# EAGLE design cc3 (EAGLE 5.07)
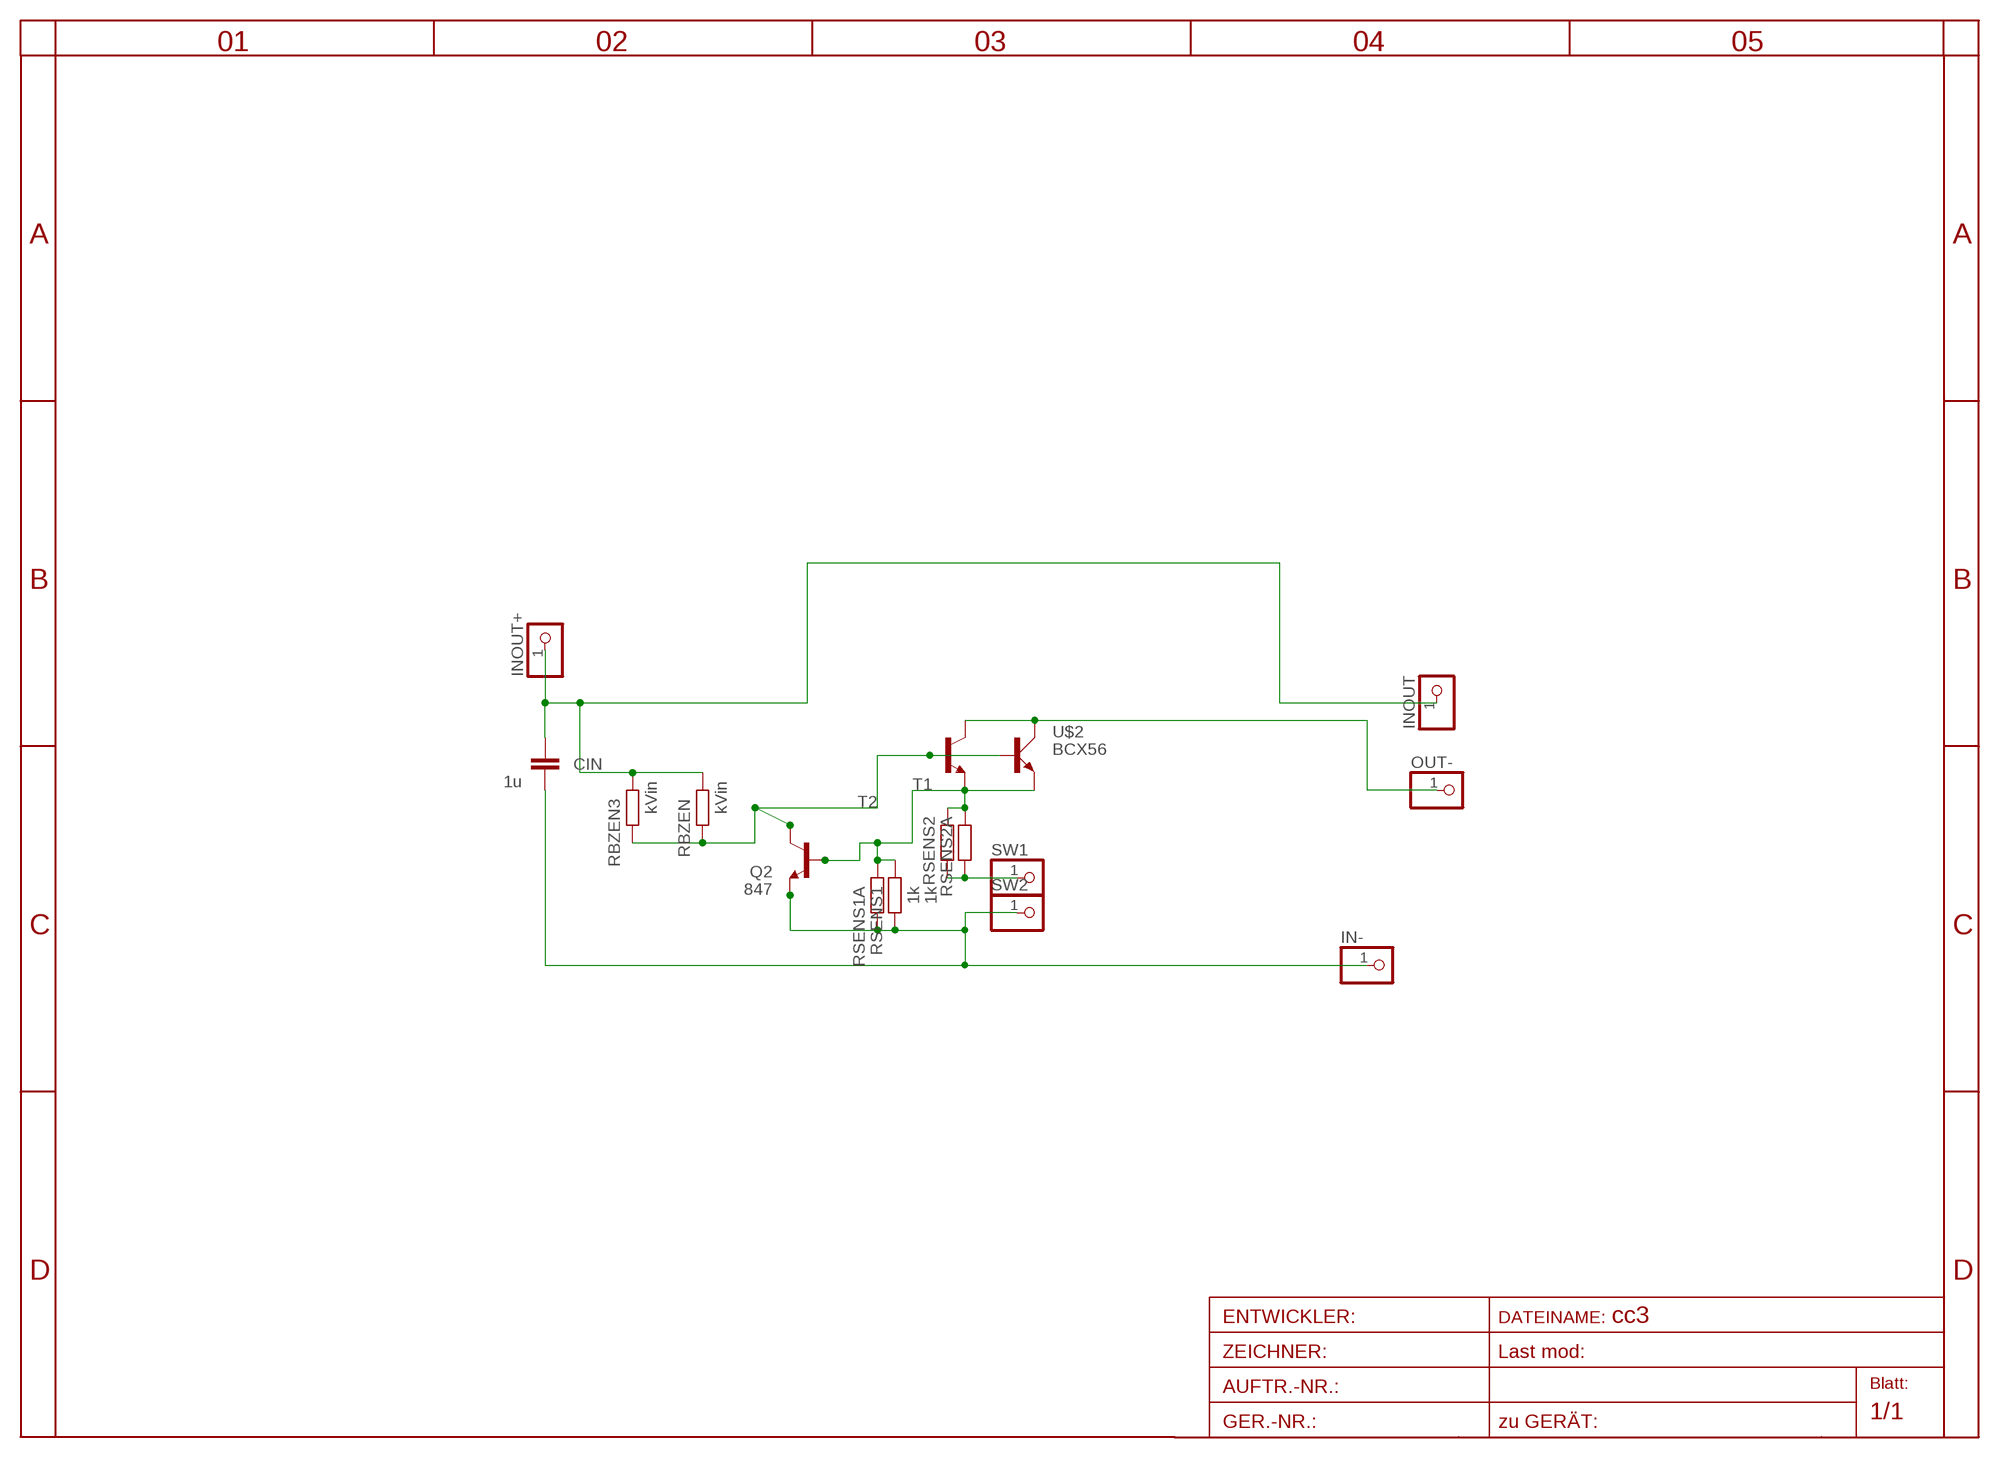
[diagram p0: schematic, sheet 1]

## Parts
CIN  1u  C-EU025-024X044  [C025-024X044]
IN-  PINHD-1X11X0.4  [1X01]
INOUT  PINHD-1X11X0.4  [1X01]
INOUT+  PINHD-1X11X0.4  [1X01]
OUT-  PINHD-1X11X0.4  [1X01]
Q2  847  BC847ASMD  [SOT23]
RBZEN  kVin  R-EU_0207/7  [0207/7]
RBZEN3  kVin  R-EU_R1206  [R1206]
RSENS1  1k  R-EU_R1206  [R1206]
RSENS1A  1k  R-EU_0204/7  [0204/7]
RSENS2  0V6/maxA  R-EU_R1210  [R1210]
RSENS2A  0.6/maxA  R-EU_0204/7  [0204/7]
SW1  PINHD-1X11X0.4  [1X01]
SW2  PINHD-1X11X0.4  [1X01]
T1  -NPN-TO126V  [TO126V]
T2  BC337-40-NPN-TO92-EBC  [TO92-EBC]
U$2  BCX56  [SOT223]

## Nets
C: OUT-.1 T1.2(C) U$2.2(C)
CB: Q2.3(C) RBZEN3.2 RBZEN.2 T1.3(B) T2.C U$2.1(B)
EB: Q2.1(B) RSENS1.1 RSENS1A.1 RSENS2.1 RSENS2A.1 T1.1(E) T2.B U$2.3(E)
GND: CIN.2 IN-.1 Q2.2(E) RSENS1.2 RSENS1A.2 SW2.1 T2.E
OUT: CIN.1 INOUT+.1 INOUT.1 RBZEN3.1 RBZEN.1
SWTCH: RSENS2.2 RSENS2A.2 SW1.1

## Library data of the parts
CIN = rcl:C-EU: CAPACITOR, European symbol
IN- INOUT INOUT+ OUT- SW1 SW2 = pinhead:PINHD-1X1: PIN HEADER
Q2 = transistor-npn:BC847*: NPN Transistor
RBZEN RBZEN3 RSENS1 RSENS1A RSENS2 RSENS2A = rcl:R-EU_: RESISTOR, European symbol
T1 T2 = transistor:*-NPN-: NPN Transistror BF959 corrected 2008.03.06
U$2 = transistor-power:BCX56

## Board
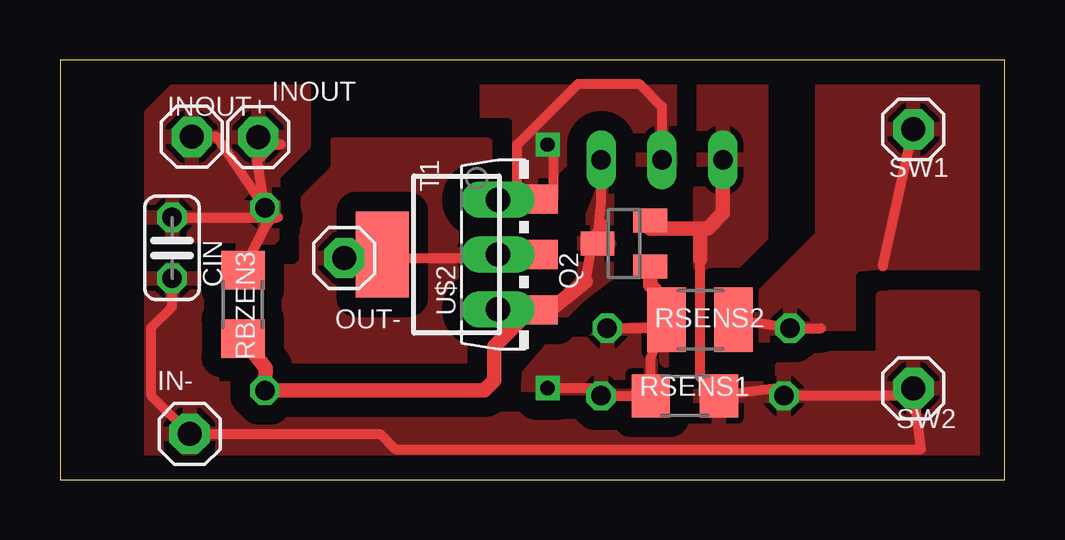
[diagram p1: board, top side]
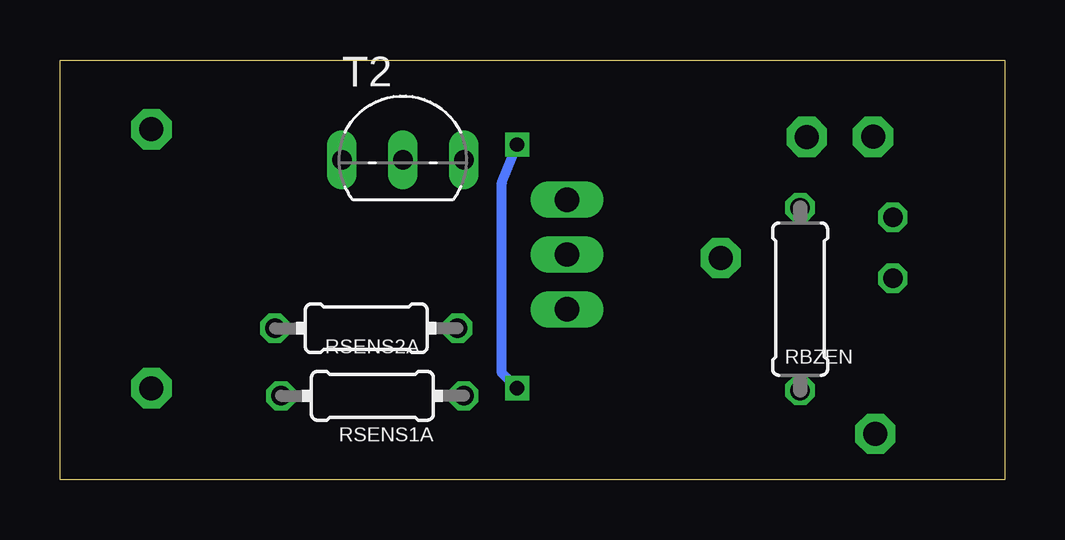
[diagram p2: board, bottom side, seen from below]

Size 39.37 x 17.5 mm. Coordinates in mm from the lower left corner, seen from the top.
Outline: 0,0 39.37,0 39.37,17.5 0,17.5 0,0
Copper layers (1*16): Top 0.035mm / dielectric 1.5mm / Bottom 0.035mm
Design rules "default *": minimum track width 10mil, minimum drill 20mil, track to track 8mil, track to pad 8mil, pad to pad 8mil, via to via 8mil, smd to smd 8mil, copper to edge 40mil, drill to drill 8mil, minimum pad ring 1mil, minimum via ring 8mil, stop-mask expansion 4mil, vias tented up to drill 0mil, thermal gap 10mil

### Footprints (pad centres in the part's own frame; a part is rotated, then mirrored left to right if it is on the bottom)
C025-024X044 = drill 0.813 octagon: 1 -1.27,0; 2 1.27,0
1X01 = drill 1 pad 1.676 octagon: 1 0,0
SOT23 = smd 1 x 1.4: 1 -0.95,-1.1; 2 0.95,-1.1; 3 0,1.1
0207/7 = drill 0.813 octagon: 1 -3.81,0; 2 3.81,0
R1206 = smd 1.6 x 1.803: 1 -1.422,0; 2 1.422,0
0204/7 = drill 0.813 octagon: 1 -3.81,0; 2 3.81,0
R1210 = smd 1.6 x 2.7: 1 -1.4,0; 2 1.4,0
TO126V = drill 1.016 long: 1 -2.286,-1.27; 2 0,-1.27; 3 2.286,-1.27
TO92-EBC = drill 0.813 long: B 0,-1.27; C 2.54,-1.27; E -2.54,-1.27
SOT223 = smd 1.219 x 2.235: 1 -2.311,-3.099; 2 0,-3.099; 3 2.311,-3.099 | smd 3.6 x 2.2: 4 0,3.099

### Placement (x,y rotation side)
CIN  4.67,9.66 270 top
IN-  5.4,1.91 0 top
INOUT  8.26,14.29 0 top
INOUT+  5.49,14.29 0 top
OUT-  11.84,9.24 0 top
Q2  23.5,9.84 90 top
RBZEN  8.53,7.53 270 bottom
RBZEN3  7.62,7.3 270 top
RSENS1  26.04,3.49 0 top
RSENS1A  26.35,3.49 180 bottom
RSENS2  26.67,6.67 0 top
RSENS2A  26.61,6.31 180 bottom
SW1  35.56,14.61 0 top
SW2  35.56,3.81 0 top
T1  19.52,9.38 270 top
T2  25.08,14.61 0 bottom
U$2  16.52,9.38 90 top

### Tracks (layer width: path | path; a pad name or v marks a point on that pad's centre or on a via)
C
  Top 0.406: OUT-.1 18.11,9.24 T1.2 U$2.2
  pour Top (isolate 0.813, rank 2): 11.43,13.97 17.78,13.97 17.78,3.81 8.89,3.81 8.89,10.16
CB
  Top 0.406: T1.3 19.6,7.1 U$2.1 19.71,6.99 20.32,6.99 | T2.C 22.54,11.58 Q2.3 22.69,10.62 22.23,10.16 21.91,8.26
  Top 0.61: RBZEN3.2 8.57,4.63 RBZEN.2 17.69,3.72 18.1,4.13 18.1,5.55 U$2.1 | 20.32,6.99 21.91,8.26
  pour Top (isolate 0.813, rank 4): 22.86,12.7 23.18,12.7 23.18,11.11 23.5,10.16 22.86,8.57 21.59,7.62 20.32,6.35
EB  (via drill 0.6)
  Top 0.406: RSENS2A.1 24.97,6.31 RSENS2.1 24.61,5.08 RSENS1.1 RSENS1A.1 22.23,3.81 v20.32,3.81 | U$2.3 20.54,11.7 20.54,13.75 v20.32,13.97 | T2.B 25.08,15.56 24.13,16.51 21.59,16.51 19.05,13.97 19.05,12.27 U$2.3 | T1.1 19.6,11.67 U$2.3
  Top 0.61: Q2.1 24.59,8.11 25.08,7.62 25.08,6.2 RSENS2.1
  Bottom 0.406: v20.32,3.81 20.95,4.45 20.95,12.38 v20.32,13.97
  pour Top (isolate 0.813, rank 3): 25.4,12.7 25.4,16.51 17.78,16.51 17.78,11.43 20.32,11.43 20.32,12.7 21.59,13.97
  pour Top (isolate 0.813, rank 5): 20.95,6.03 25.08,6.35 25.08,3.81 19.05,3.81
GND
  Top 0.406: CIN.2 4.67,7.21 3.81,6.35 3.81,3.49 IN-.1 13.34,1.91 13.97,1.27 35.88,1.27 SW2.1 34.92,3.49 RSENS1A.2 29.84,3.81 RSENS1.2 26.67,4.28 26.67,9.21
  Top 0.61: T2.E 27.62,11.11 26.99,10.48 26.67,10.48 | 26.67,10.48 24.6,10.48 Q2.2 | 26.67,9.21 26.67,10.48
  pour Top (isolate 0.813, rank 2): 3.81,8.89 6.35,8.89 6.35,3.81 15.24,3.81 16.51,2.54 26.67,2.54 26.67,3.81 29.21,3.81 30.48,5.08 34.29,5.08 34.29,7.62 38.1,7.62 38.1,0 3.81,0
  pour Top (isolate 0.813, rank 5): 26.67,16.51 29.21,16.51 29.21,10.16 27.94,8.89 26.67,8.89 26.67,12.7
OUT
  Top 0.406: INOUT+.1 6.53,14.29 RBZEN.1 | RBZEN.1 8.21,13.29 8.89,13.97 9.21,13.97 INOUT.1 | CIN.1 8.89,10.94 | 8.89,10.94 9.08,10.94 RBZEN.1 | RBZEN3.1 8.57,10.62 8.89,10.94
  pour Top (isolate 0.813): 3.81,15.24 5.08,16.51 10.16,16.51 10.16,13.97 8.89,12.7 8.89,10.16 7.62,8.89 7.62,10.16 3.81,10.16
SWTCH
  Top 0.406: RSENS2.2 30.46,6.35 | 30.46,6.35 30.48,6.35 | 30.46,6.35 RSENS2A.2 | RSENS2A.2 30.14,6.03 | RSENS2A.2 31.71,6.31 | 34.29,8.89 SW1.1
  pour Top (isolate 0.813, rank 3): 31.75,16.51 38.1,16.51 38.1,8.89 35.56,8.89 31.75,5.08 29.21,5.08 29.21,7.62 31.75,10.16

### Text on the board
tStop: MICHAEL5.net
bStop: MICHAEL5.net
